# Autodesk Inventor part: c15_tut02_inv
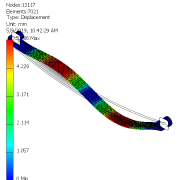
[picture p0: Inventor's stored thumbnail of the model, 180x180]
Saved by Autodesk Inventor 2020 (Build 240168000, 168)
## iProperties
Created: 2017-05
Part Number: c15_tut02_inv
Material: Steel, Mild
Document SubType Name: Modeling
Designer: CADCIM 00
Mass: 5.6491 g
Surface Area: 16.9114 cm^2
Volume: 0.71963 cm^3
Density: 7.85 g/cm^3
Appearance: Semi-Polished
Author: CADCIM 00
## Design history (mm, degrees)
sketch "Sketch1"
  geometry: L1 (0, 0)-(0, 18.068); L2 (48.5, 8.9)-(47.5, 8.9); L3 (-48.5, 8.9)-(-47.5, 8.9); A1 r 200 centre (0, 201) between (-50.378, 7.449) and (50.378, 7.449); A2 r 201 centre (0, 201) between (-50.63, 6.481) and (50.63, 6.481); A3 r 1.5 centre (50, 8.9) between (50.378, 7.449) and (48.5, 8.9); A4 r 2.5 centre (50, 8.9) between (50.63, 6.481) and (47.5, 8.9); A5 r 1.5 centre (-50, 8.9) between (-48.5, 8.9) and (-50.378, 7.449); A6 r 2.5 centre (-50, 8.9) between (-47.5, 8.9) and (-50.63, 6.481); 5 further points
  constraints: 13 point on circle, 6 centre point, 6 end point, 6 symmetric about line, 5 horizontal alignment, 3 coincident, 2 tangent, 1 horizontal, 1 midpoint, 1 vertical, 2 other
  dimensions: "d0" = 200 radius of A1; "d1" = 1 radial gap between concentric circles of A2 A1; "d2" = 2.5 radius of A4; "d3" = 50 distance from line of L1 A3.centre
extrude "Extrusion1" new body sketch "Sketch1" distance "d4" = 6; taper "d5" = 0 deg
body "Solid1"
